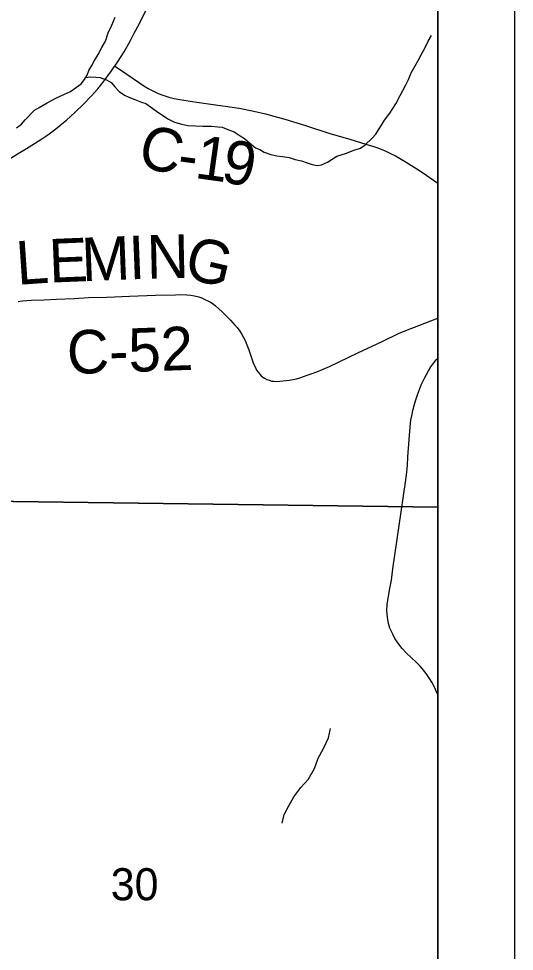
# Model space of a CAD drawing. Extents: x 0 to 34, y 0 to 22.
# Drawn here: x 16.854 to 17.5, y 18.301 to 19.518 of the extents above; entities that cross this region are included whole.
import ezdxf

# ---------------------------------------------------------------- set-up
doc = ezdxf.new("R2010")
doc.units = 0
for name, color, linetype in [('GM_X_Corporation', 7, 'Continuous'), ('GM_X_County_Road', 7, 'Continuous'), ('GM_X_County_Road_Text', 7, 'Continuous'), ('GM_X_Minor_River', 7, 'Continuous'), ('GM_X_Section_Text', 7, 'Continuous'), ('GM_X_State_Route', 7, 'Continuous'), ('SH_Data', 7, 'Continuous')]:
    doc.layers.add(name, color=color, linetype=linetype)

msp = doc.modelspace()

# ---------------------------------------------------------------- linework, layer by layer
at = {"layer": 'GM_X_Corporation'}
for points in [[(17.4, 16.913), (17.4, 20.4), (16.7661, 20.4), (16.7652, 20.328), (16.7547, 19.2837), (16.7532, 19.0614), (16.752, 18.8891), (16.5475, 18.8929), (16.5174, 18.8935), (16.5168, 18.8707), (16.4886, 17.7392), (16.4807, 17.4161), (16.4704, 17.0104), (16.4703, 17.0036), (16.4689, 16.9245), (16.5516, 16.9243)], [(17.4, 18.8808), (17.4, 19.8932), (16.7598, 19.9006), (16.7485, 18.8896)], [(17.4, 17.9189), (17.4, 18.8808), (16.7485, 18.8896), (16.5138, 18.8938), (16.4906, 17.9114)]]:
    msp.add_lwpolyline(points, close=True, dxfattribs=at)
at = {"layer": 'GM_X_County_Road'}
for points in [[(16.979, 19.4562), (16.9875, 19.4504), (17.0166, 19.4304), (17.0223, 19.4271), (17.0283, 19.4239), (17.0355, 19.4207), (17.0417, 19.4183), (17.0493, 19.4159), (17.0562, 19.4141), (17.0665, 19.4121), (17.077, 19.4105), (17.0891, 19.4087), (17.1411, 19.4012), (17.1602, 19.3975), (17.1755, 19.394), (17.1861, 19.3911), (17.2006, 19.3869), (17.2261, 19.379), (17.2593, 19.3684), (17.2855, 19.3608), (17.3062, 19.3545), (17.3192, 19.3504), (17.3263, 19.3478), (17.3323, 19.3454), (17.3386, 19.3424), (17.3452, 19.3391), (17.3504, 19.3361), (17.3589, 19.3311), (17.3727, 19.3223), (17.3815, 19.3165), (17.3901, 19.3105), (17.3988, 19.3044), (17.4, 19.3036)], [(16.853, 19.1492), (16.8585, 19.1499), (16.87, 19.1507), (16.8869, 19.1514), (16.9027, 19.152), (16.9261, 19.1531), (16.9446, 19.1542), (16.9687, 19.1547), (16.998, 19.1561), (17.032, 19.1574), (17.0582, 19.158), (17.0645, 19.1581), (17.0728, 19.1579), (17.078, 19.1575), (17.083, 19.1567), (17.0883, 19.1553), (17.0922, 19.1537), (17.0964, 19.1519), (17.1001, 19.1502), (17.1036, 19.1484), (17.1073, 19.1459), (17.1104, 19.1433), (17.1142, 19.1398), (17.1195, 19.135), (17.125, 19.1295), (17.1297, 19.1246), (17.136, 19.1178), (17.1383, 19.1152), (17.1418, 19.1105), (17.1443, 19.1071), (17.1468, 19.1023), (17.1489, 19.0983), (17.1503, 19.0949), (17.1536, 19.0861), (17.16, 19.0678), (17.1618, 19.0638), (17.1639, 19.0597), (17.1657, 19.0571), (17.1679, 19.0543), (17.1699, 19.0523), (17.1718, 19.0506), (17.1741, 19.049), (17.1774, 19.0474), (17.1804, 19.0463), (17.1837, 19.0453), (17.1865, 19.045), (17.1896, 19.0449), (17.2067, 19.0463), (17.2158, 19.0484), (17.2203, 19.0496), (17.2252, 19.0514), (17.2296, 19.0529), (17.2349, 19.0547), (17.2423, 19.0573), (17.2588, 19.0641), (17.2717, 19.0703), (17.2957, 19.0821), (17.3275, 19.0969), (17.3489, 19.1072), (17.3608, 19.1122), (17.3754, 19.1179), (17.3909, 19.1238), (17.4, 19.1274)], [(17.4, 18.636), (17.396, 18.6458), (17.3925, 18.6526), (17.3885, 18.6585), (17.3849, 18.6636), (17.3816, 18.6679), (17.3774, 18.6731), (17.3716, 18.6792), (17.3659, 18.6844), (17.3593, 18.6905), (17.3539, 18.6962), (17.3492, 18.702), (17.3441, 18.7095), (17.3414, 18.7149), (17.3378, 18.7228), (17.3358, 18.7291), (17.3345, 18.7373), (17.3338, 18.7456), (17.334, 18.7538), (17.337, 18.7727), (17.3396, 18.7854), (17.3417, 18.8003), (17.3581, 18.9133), (17.3596, 18.9264), (17.3606, 18.9353), (17.3613, 18.9464), (17.3634, 18.9744), (17.3647, 18.9903), (17.3651, 18.9944), (17.3661, 18.9999), (17.3676, 19.0067), (17.3694, 19.0133), (17.3712, 19.0194), (17.3737, 19.0275), (17.3761, 19.0343), (17.3786, 19.0404), (17.383, 19.0493), (17.3881, 19.0588), (17.3911, 19.0637), (17.3948, 19.0689), (17.3979, 19.0728), (17.4, 19.0751)]]:
    msp.add_lwpolyline(points, dxfattribs=at)
at = {"layer": 'GM_X_Minor_River'}
for points in [[(16.9352, 19.4329), (16.9394, 19.4386), (16.9428, 19.4443), (16.9451, 19.4503), (16.949, 19.4572), (16.9524, 19.4636), (16.9574, 19.4712), (16.962, 19.4803), (16.9669, 19.4886), (16.9704, 19.4996), (16.975, 19.5095), (16.9792, 19.5201)], [(16.941, 19.4412), (16.9474, 19.4424), (16.9542, 19.4419), (16.9599, 19.4415), (16.9682, 19.4385), (16.9743, 19.435), (16.9788, 19.4293), (16.9845, 19.4232), (16.9917, 19.4183), (16.9974, 19.4156), (17.0049, 19.4125), (17.0136, 19.4091), (17.0193, 19.4075), (17.0254, 19.4033), (17.0333, 19.3976), (17.0417, 19.3919), (17.0488, 19.3869), (17.0568, 19.3831), (17.0663, 19.3804), (17.0742, 19.3788), (17.0841, 19.3784), (17.0936, 19.378), (17.105, 19.3779), (17.1133, 19.3771), (17.119, 19.3764), (17.1285, 19.3725), (17.1345, 19.3706), (17.1425, 19.3653), (17.1481, 19.3618), (17.1546, 19.3561), (17.1625, 19.3496), (17.1682, 19.3473), (17.1739, 19.3439), (17.1822, 19.3408), (17.1902, 19.3392), (17.1978, 19.3385), (17.2061, 19.3369), (17.2141, 19.3346), (17.2224, 19.3327), (17.23, 19.33), (17.2364, 19.328), (17.2429, 19.3265), (17.2486, 19.3276), (17.2562, 19.331), (17.2622, 19.3348), (17.2683, 19.3386), (17.2809, 19.3427), (17.2908, 19.3465), (17.2995, 19.3491), (17.3056, 19.3536), (17.3143, 19.362), (17.3193, 19.3676), (17.3227, 19.3733), (17.3269, 19.379), (17.3308, 19.3858), (17.3376, 19.3949), (17.3453, 19.407), (17.351, 19.418), (17.3579, 19.4309), (17.3621, 19.4389), (17.3656, 19.4473), (17.3705, 19.4567), (17.3744, 19.4636), (17.3786, 19.4711), (17.3835, 19.4806), (17.3874, 19.4886), (17.392, 19.4962)], [(16.8507, 19.3758), (16.8572, 19.3804), (16.8618, 19.3861), (16.8743, 19.3989), (16.8804, 19.4023), (16.8907, 19.4084), (16.9029, 19.4148), (16.9131, 19.4197), (16.9211, 19.4231), (16.9291, 19.4287), (16.9352, 19.4329)], [(17.1973, 18.4683), (17.1996, 18.4796), (17.2061, 18.4918), (17.2125, 18.5028), (17.2217, 18.5149), (17.2312, 18.5255), (17.2395, 18.5396), (17.2441, 18.5532), (17.2513, 18.5661), (17.2574, 18.5798), (17.2601, 18.5919)]]:
    msp.add_lwpolyline(points, dxfattribs=at)
at = {"layer": 'GM_X_State_Route'}
msp.add_lwpolyline([(16.8105, 19.3168), (16.8638, 19.3489), (16.8741, 19.3552), (16.8837, 19.3612), (16.8916, 19.3667), (16.9002, 19.3729), (16.9065, 19.3779), (16.91, 19.3809), (16.9158, 19.3859), (16.9271, 19.396), (16.9376, 19.4061), (16.9483, 19.4173), (16.9566, 19.4266), (16.962, 19.4332), (16.97, 19.4435), (16.9747, 19.45), (16.9774, 19.4539), (16.979, 19.4562), (16.9824, 19.4614), (16.9909, 19.4747), (16.9993, 19.4897), (17.0043, 19.4992), (17.0109, 19.5119), (17.0236, 19.5373)], dxfattribs=at)
at = {"layer": 'SH_Data'}
for points in [[(10.5, 20.5), (17.5, 20.5), (17.5, 13.5), (10.5, 13.5)], [(10.6, 20.4), (17.4, 20.4), (17.4, 13.6), (10.6, 13.6)]]:
    msp.add_lwpolyline(points, close=True, dxfattribs=at)

# ---------------------------------------------------------------- texts
at = {"layer": 'GM_X_County_Road_Text'}
for s, height, rotation, p in [('C', 0.0568, 345.5103, (17.0065, 19.3268)), ('1', 0.0568, 352.023, (17.0818, 19.3105)), ('9', 0.0568, 349.4708, (17.1158, 19.3058)), ('-', 0.0568, 352.1804, (17.0588, 19.3137)), ('L', 0.0568, 3.9501, (16.852, 19.1708)), ('E', 0.0568, 2.3406, (16.894, 19.1737)), ('M', 0.0568, 2.2749, (16.9365, 19.1754)), ('I', 0.0568, 2.2722, (16.9981, 19.1779)), ('N', 0.0568, 1.2823, (17.0211, 19.1788)), ('G', 0.0568, 346.7351, (17.0674, 19.1803)), ('C-52', 0.05682, 2.0542, (16.9174, 19.0542))]:
    msp.add_text(s, height=height, rotation=rotation, dxfattribs=at).set_placement(p)
at = {"layer": 'GM_X_Section_Text'}
msp.add_text('30', height=0.04186, rotation=0, dxfattribs=at).set_placement((16.9736, 18.3679))

doc.saveas('drawing.dxf')
